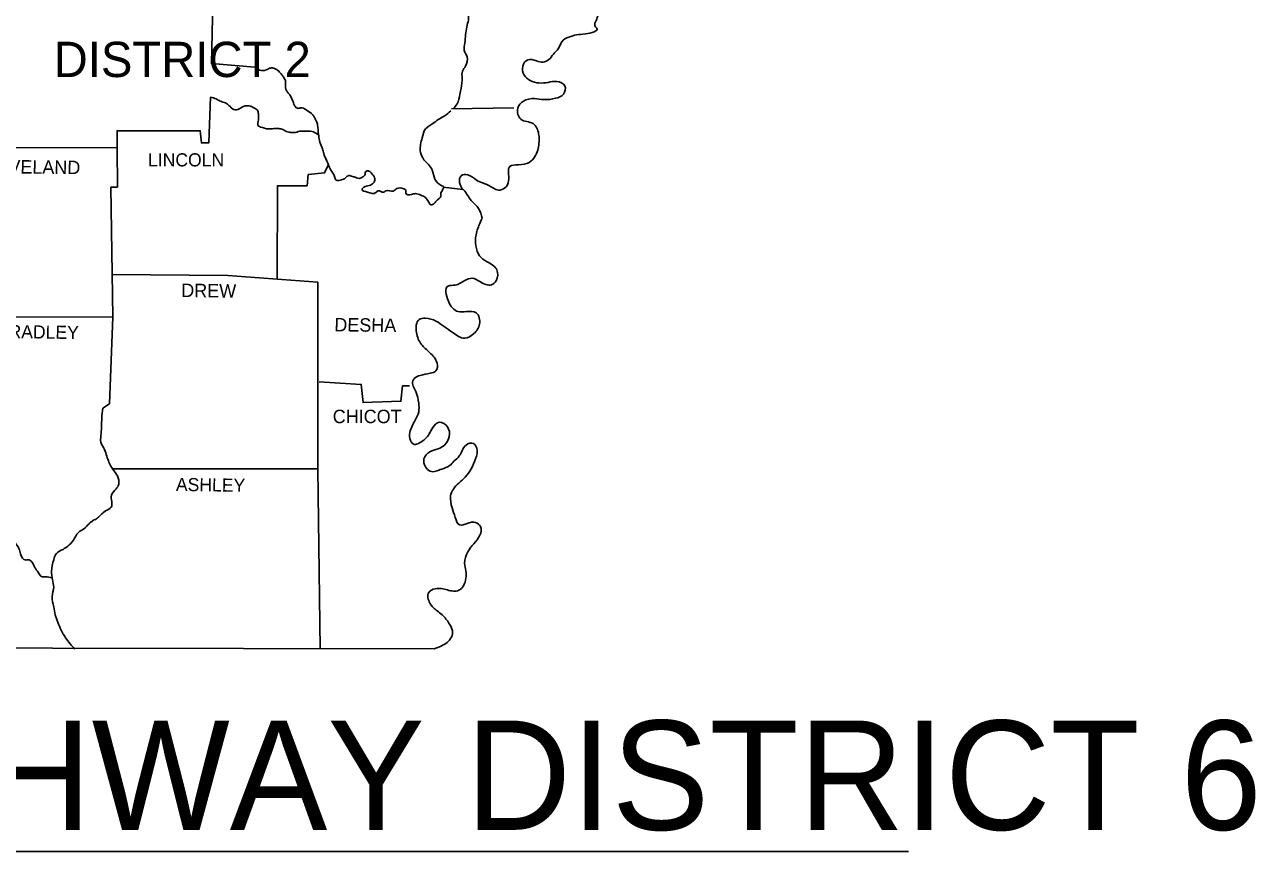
# Model space of a CAD drawing. Extents: x 1127717 to 1741049, y 2026793 to 2244711.
# Drawn here: x 1371845 to 1391538, y 2119549 to 2132784 of the extents above; entities that cross this region are included whole.
import ezdxf

# ---------------------------------------------------------------- set-up
doc = ezdxf.new("R2010")
doc.units = 0
doc.layers.add('R_Draft', color=7, linetype='Continuous')

msp = doc.modelspace()

# ---------------------------------------------------------------- linework, layer by layer
at = {"layer": 'R_Draft'}
for p, q in [((1378675, 2131434), (1379675, 2131449)), ((1376520, 2131034), (1376548, 2131018)), ((1378855, 2130144), (1378540, 2130184)), ((1352928, 2119549), (1385989, 2119549))]:
    msp.add_line(p, q, dxfattribs=at)
for points in [[(1374876, 2134122), (1374835, 2132159), (1375530, 2132104)], [(1374820, 2131624), (1374790, 2130889), (1374675, 2130889), (1374655, 2131084), (1373325, 2131084), (1373325, 2130804)], [(1371545, 2130819), (1373315, 2130809)], [(1373325, 2130809), (1373330, 2130184), (1373225, 2130179), (1373255, 2128104)], [(1376705, 2130544), (1376645, 2130409), (1376380, 2130384), (1376365, 2130204), (1375890, 2130204), (1375885, 2128709)], [(1373240, 2128784), (1375095, 2128769), (1376535, 2128659)], [(1376535, 2128659), (1376535, 2125669), (1376575, 2122794)], [(1370995, 2128099), (1373255, 2128104)], [(1373255, 2128104), (1373205, 2126714), (1373095, 2126644)], [(1376560, 2127064), (1377230, 2127024), (1377260, 2126734), (1377865, 2126754), (1377890, 2126999), (1378005, 2126999)], [(1378400, 2122794), (1360075, 2122824), (1360065, 2126869)], [(1373253, 2125674), (1376535, 2125674)]]:
    msp.add_lwpolyline(points, dxfattribs=at)
for points in [[(1382610, 2136299), (1382495, 2136154), (1382325, 2136244), (1382325, 2136364), (1382350, 2136489), (1382290, 2136569), (1382185, 2136534), (1382185, 2136379), (1382175, 2136229), (1382145, 2136014), (1382215, 2135949), (1382375, 2135929), (1382490, 2135899), (1382560, 2135784), (1382555, 2135644), (1382500, 2135509), (1382420, 2135399), (1382295, 2135359), (1382195, 2135424), (1382155, 2135554), (1382110, 2135669), (1382025, 2135754), (1381935, 2135659), (1381915, 2135484), (1381920, 2135334), (1381920, 2135129), (1382050, 2134994), (1382130, 2134839), (1382105, 2134699), (1382010, 2134534), (1381970, 2134389), (1381930, 2134194), (1381935, 2133979), (1381900, 2133769), (1381830, 2133629), (1381700, 2133514), (1381615, 2133439), (1381545, 2133364), (1381510, 2133214), (1381485, 2133109), (1381390, 2132984), (1381315, 2132974), (1381255, 2133024), (1381235, 2133109), (1381235, 2133194), (1381195, 2133279), (1381070, 2133314), (1380970, 2133309), (1380925, 2133239), (1380990, 2133044), (1381015, 2132919), (1380980, 2132749), (1381000, 2132729), (1380820, 2132634), (1380675, 2132619), (1380555, 2132584), (1380440, 2132509), (1380385, 2132399), (1380305, 2132309), (1380235, 2132224), (1380140, 2132184), (1380035, 2132204), (1379895, 2132219), (1379815, 2132119), (1379840, 2131974), (1379935, 2131889), (1380075, 2131849), (1380220, 2131859), (1380360, 2131874), (1380490, 2131804), (1380465, 2131669), (1380340, 2131604), (1380155, 2131584), (1380005, 2131599), (1379825, 2131559), (1379735, 2131444), (1379785, 2131269), (1379980, 2131199), (1380070, 2131034), (1380075, 2130879), (1380010, 2130674), (1379920, 2130579), (1379745, 2130539), (1379610, 2130514), (1379590, 2130284), (1379530, 2130169), (1379425, 2130134), (1379275, 2130209), (1379185, 2130244), (1379075, 2130294), (1378935, 2130379), (1378830, 2130364), (1378860, 2130144), (1378870, 2130134), (1378990, 2129969), (1379110, 2129839), (1379165, 2129684)], [(1382610, 2136299), (1382495, 2136154), (1382325, 2136244), (1382325, 2136364), (1382350, 2136489), (1382290, 2136569), (1382185, 2136534), (1382185, 2136379), (1382175, 2136229), (1382145, 2136014), (1382215, 2135949), (1382375, 2135929), (1382490, 2135899), (1382560, 2135784), (1382555, 2135644), (1382500, 2135509), (1382420, 2135399), (1382295, 2135359), (1382195, 2135424), (1382155, 2135554), (1382110, 2135669), (1382025, 2135754), (1381935, 2135659), (1381915, 2135484), (1381920, 2135334), (1381920, 2135129), (1382050, 2134994), (1382130, 2134839), (1382105, 2134699), (1382010, 2134534), (1381970, 2134389), (1381930, 2134194), (1381935, 2133979), (1381900, 2133769), (1381830, 2133629), (1381700, 2133514), (1381615, 2133439), (1381545, 2133364), (1381510, 2133214), (1381485, 2133109), (1381390, 2132984), (1381315, 2132974), (1381255, 2133024), (1381235, 2133109), (1381235, 2133194), (1381195, 2133279), (1381070, 2133314), (1380970, 2133309), (1380925, 2133239), (1380990, 2133044), (1381015, 2132919), (1380980, 2132749), (1381000, 2132729), (1380820, 2132634), (1380675, 2132619), (1380555, 2132584), (1380440, 2132509), (1380385, 2132399), (1380305, 2132309), (1380235, 2132224), (1380140, 2132184), (1380035, 2132204), (1379895, 2132219), (1379815, 2132119), (1379840, 2131974), (1379935, 2131889), (1380075, 2131849), (1380220, 2131859), (1380360, 2131874), (1380490, 2131804), (1380465, 2131669), (1380340, 2131604), (1380155, 2131584), (1380005, 2131599), (1379825, 2131559), (1379735, 2131444), (1379785, 2131269), (1379980, 2131199), (1380070, 2131034), (1380075, 2130879), (1380010, 2130674), (1379920, 2130579), (1379745, 2130539), (1379610, 2130514), (1379590, 2130284), (1379530, 2130169), (1379425, 2130134), (1379275, 2130209), (1379185, 2130244), (1379075, 2130294), (1378935, 2130379), (1378830, 2130364), (1378860, 2130144), (1378870, 2130134), (1378990, 2129969), (1379110, 2129839), (1379165, 2129684)], [(1378700, 2131434), (1378765, 2131514), (1378810, 2131669), (1378830, 2131764), (1378845, 2131929), (1378850, 2132039), (1378900, 2132119), (1378925, 2132269), (1378880, 2132369), (1378890, 2132489), (1378900, 2132624), (1378920, 2132744), (1378945, 2132859), (1378945, 2132934), (1378880, 2133034), (1378780, 2133099), (1378700, 2133124), (1378650, 2133159), (1378580, 2133219), (1378510, 2133339), (1378470, 2133384), (1378390, 2133489), (1378310, 2133549), (1378260, 2133684), (1378180, 2133779), (1378070, 2133819), (1377990, 2133904), (1377960, 2134034), (1377910, 2134114), (1377840, 2134164), (1377725, 2134234), (1377640, 2134284), (1377615, 2134399), (1377565, 2134454), (1377445, 2134484), (1377430, 2134689)], [(1375530, 2132104), (1375605, 2132054), (1375710, 2132059), (1375780, 2132089), (1375835, 2132084), (1375910, 2132039), (1375960, 2131979), (1375995, 2131934), (1376020, 2131864), (1376020, 2131799), (1376045, 2131709), (1376075, 2131674), (1376115, 2131609), (1376140, 2131549), (1376155, 2131509), (1376210, 2131444), (1376260, 2131449), (1376305, 2131444), (1376365, 2131409), (1376455, 2131339), (1376470, 2131319), (1376530, 2131189), (1376540, 2131109), (1376550, 2131004), (1376570, 2130904), (1376610, 2130794), (1376630, 2130719), (1376675, 2130614), (1376705, 2130544), (1376745, 2130454), (1376805, 2130354), (1376830, 2130294), (1376915, 2130299), (1376975, 2130324), (1377020, 2130364), (1377075, 2130359), (1377135, 2130339), (1377215, 2130324), (1377265, 2130354), (1377290, 2130374), (1377295, 2130419), (1377340, 2130444), (1377390, 2130409), (1377445, 2130329), (1377445, 2130279), (1377425, 2130249), (1377360, 2130209), (1377270, 2130179), (1377245, 2130144), (1377330, 2130104), (1377465, 2130094), (1377500, 2130124), (1377590, 2130099), (1377625, 2130124), (1377745, 2130119), (1377800, 2130159), (1377910, 2130154), (1377945, 2130129), (1377945, 2130084), (1378035, 2130064), (1378100, 2130079), (1378185, 2130054), (1378260, 2130014), (1378300, 2129959), (1378350, 2129899), (1378395, 2129914), (1378430, 2129959), (1378505, 2130039), (1378505, 2130089), (1378525, 2130124), (1378550, 2130174)], [(1374820, 2131624), (1374910, 2131594), (1374975, 2131559), (1375060, 2131529), (1375115, 2131489), (1375190, 2131424), (1375280, 2131434), (1375345, 2131474), (1375410, 2131484), (1375460, 2131479), (1375515, 2131449), (1375575, 2131404), (1375585, 2131339), (1375585, 2131264), (1375585, 2131159), (1375620, 2131144), (1375745, 2131114), (1375830, 2131119), (1375910, 2131119), (1375975, 2131104), (1376030, 2131074), (1376070, 2131064), (1376130, 2131054), (1376180, 2131059), (1376265, 2131079), (1376315, 2131079), (1376395, 2131079), (1376445, 2131074), (1376520, 2131034)], [(1378555, 2130189), (1378520, 2130204), (1378410, 2130309), (1378365, 2130459), (1378305, 2130544), (1378215, 2130649), (1378175, 2130769), (1378205, 2130969), (1378260, 2131114), (1378375, 2131199), (1378470, 2131269), (1378560, 2131319), (1378665, 2131404)], [(1379165, 2129684), (1379115, 2129569), (1379060, 2129369), (1379075, 2129199), (1379150, 2129054), (1379270, 2128974), (1379400, 2128859), (1379390, 2128684), (1379315, 2128619), (1379140, 2128664), (1379005, 2128724), (1378890, 2128689), (1378735, 2128614), (1378620, 2128599), (1378625, 2128359), (1378780, 2128189), (1378915, 2128189), (1379070, 2128169), (1379125, 2127989), (1379035, 2127839), (1378885, 2127764), (1378695, 2127854), (1378560, 2127949), (1378425, 2128039), (1378255, 2128084), (1378160, 2128064), (1378115, 2127854), (1378195, 2127664), (1378325, 2127534), (1378445, 2127364), (1378425, 2127239), (1378335, 2127204), (1378175, 2127169), (1378080, 2127119), (1378055, 2127079), (1378105, 2126909), (1378150, 2126724), (1378150, 2126584), (1378095, 2126454), (1378010, 2126254), (1378020, 2126124), (1378080, 2126064), (1378155, 2126084), (1378255, 2126154), (1378320, 2126234), (1378375, 2126334), (1378480, 2126419), (1378610, 2126344), (1378640, 2126189), (1378565, 2126054), (1378460, 2125994), (1378330, 2125944), (1378235, 2125834), (1378260, 2125704), (1378335, 2125634), (1378520, 2125669), (1378645, 2125724), (1378715, 2125794), (1378800, 2125879), (1378845, 2125964), (1378910, 2126054), (1379025, 2126079), (1379080, 2126004), (1379060, 2125834), (1378990, 2125674), (1378895, 2125539), (1378790, 2125444), (1378660, 2125239), (1378685, 2125049), (1378735, 2124894), (1378805, 2124774), (1378925, 2124799), (1379060, 2124814), (1379140, 2124749), (1379130, 2124609), (1379030, 2124474), (1378935, 2124344), (1378885, 2124164), (1378905, 2124039), (1378905, 2123924), (1378865, 2123799), (1378795, 2123729), (1378610, 2123734), (1378415, 2123754), (1378310, 2123694), (1378330, 2123524), (1378445, 2123399), (1378525, 2123334), (1378640, 2123194), (1378690, 2123079), (1378675, 2122979), (1378605, 2122894), (1378400, 2122794)], [(1379165, 2129684), (1379115, 2129569), (1379060, 2129369), (1379075, 2129199), (1379150, 2129054), (1379270, 2128974), (1379400, 2128859), (1379390, 2128684), (1379315, 2128619), (1379140, 2128664), (1379005, 2128724), (1378890, 2128689), (1378735, 2128614), (1378620, 2128599), (1378625, 2128359), (1378780, 2128189), (1378915, 2128189), (1379070, 2128169), (1379125, 2127989), (1379035, 2127839), (1378885, 2127764), (1378695, 2127854), (1378560, 2127949), (1378425, 2128039), (1378255, 2128084), (1378160, 2128064), (1378115, 2127854), (1378195, 2127664), (1378325, 2127534), (1378445, 2127364), (1378425, 2127239), (1378335, 2127204), (1378175, 2127169), (1378080, 2127119), (1378055, 2127079), (1378105, 2126909), (1378150, 2126724), (1378150, 2126584), (1378095, 2126454), (1378010, 2126254), (1378020, 2126124), (1378080, 2126064), (1378155, 2126084), (1378255, 2126154), (1378320, 2126234), (1378375, 2126334), (1378480, 2126419), (1378610, 2126344), (1378640, 2126189), (1378565, 2126054), (1378460, 2125994), (1378330, 2125944), (1378235, 2125834), (1378260, 2125704), (1378335, 2125634), (1378520, 2125669), (1378645, 2125724), (1378715, 2125794), (1378800, 2125879), (1378845, 2125964), (1378910, 2126054), (1379025, 2126079), (1379080, 2126004), (1379060, 2125834), (1378990, 2125674), (1378895, 2125539), (1378790, 2125444), (1378660, 2125239), (1378685, 2125049), (1378735, 2124894), (1378805, 2124774), (1378925, 2124799), (1379060, 2124814), (1379140, 2124749), (1379130, 2124609), (1379030, 2124474), (1378935, 2124344), (1378885, 2124164), (1378905, 2124039), (1378905, 2123924), (1378865, 2123799), (1378795, 2123729), (1378610, 2123734), (1378415, 2123754), (1378310, 2123694), (1378330, 2123524), (1378445, 2123399), (1378525, 2123334), (1378640, 2123194), (1378690, 2123079), (1378675, 2122979), (1378605, 2122894), (1378400, 2122794)], [(1373095, 2126644), (1373080, 2126489), (1373075, 2126344), (1373065, 2126204), (1373065, 2126099), (1373125, 2125984), (1373160, 2125874), (1373195, 2125779), (1373265, 2125654), (1373330, 2125559), (1373350, 2125424), (1373310, 2125354), (1373235, 2125249), (1373230, 2125059), (1373140, 2124999), (1373025, 2124899), (1372960, 2124854), (1372890, 2124809), (1372815, 2124729), (1372705, 2124654), (1372625, 2124529), (1372535, 2124434), (1372460, 2124384), (1372355, 2124319), (1372310, 2124219), (1372275, 2124034), (1372290, 2123899), (1372310, 2123779), (1372285, 2123629), (1372310, 2123464), (1372335, 2123334), (1372375, 2123219), (1372430, 2123089), (1372500, 2122969), (1372650, 2122784)], [(1368110, 2125489), (1368190, 2125544), (1368265, 2125574), (1368340, 2125559), (1368420, 2125549), (1368490, 2125559), (1368580, 2125544), (1368655, 2125499), (1368740, 2125464), (1368825, 2125464), (1368900, 2125464), (1368965, 2125419), (1369085, 2125424), (1369185, 2125464), (1369285, 2125494), (1369420, 2125509), (1369540, 2125424), (1369625, 2125354), (1369695, 2125274), (1369745, 2125184), (1369800, 2125134), (1369890, 2125099), (1369960, 2125084), (1370045, 2125059), (1370090, 2125039), (1370130, 2124944), (1370195, 2124814), (1370320, 2124769), (1370475, 2124829), (1370600, 2124864), (1370690, 2124894), (1370745, 2124914), (1370795, 2124919), (1370780, 2124929), (1370840, 2124944), (1370895, 2124904), (1370930, 2124849), (1370990, 2124769), (1371045, 2124699), (1371100, 2124674), (1371155, 2124704), (1371230, 2124679), (1371295, 2124654), (1371370, 2124634), (1371435, 2124629), (1371520, 2124609), (1371585, 2124574), (1371645, 2124539), (1371705, 2124474), (1371765, 2124374), (1371785, 2124294), (1371855, 2124214), (1371920, 2124214), (1372015, 2124084), (1372050, 2124034), (1372125, 2123944), (1372180, 2123944), (1372285, 2123924)]]:
    msp.add_spline(points, degree=3, dxfattribs=at)

# ---------------------------------------------------------------- texts
for s, height, p in [('DISTRICT 2', 565, (1372310, 2131944)), ('LINCOLN', 210, (1373820, 2130514)), ('CHICOT', 215, (1376775, 2126404)), ('ARKANSAS HIGHWAY DISTRICT 6', 1750, (1353673, 2119894))]:
    msp.add_text(s, height=height, dxfattribs=at).set_placement(p)
for s, height, rotation, p in [('CLEVELAND', 215, 359.3376, (1371025, 2130409)), ('DREW', 215, 359.2258, (1374350, 2128424)), ('DESHA', 215, 359.3704, (1376800, 2127874)), ('BRADLEY', 210, 359.1449, (1371400, 2127769)), ('ASHLEY', 210, 359.2361, (1374265, 2125319))]:
    msp.add_text(s, height=height, rotation=rotation, dxfattribs=at).set_placement(p)

doc.saveas('drawing.dxf')
